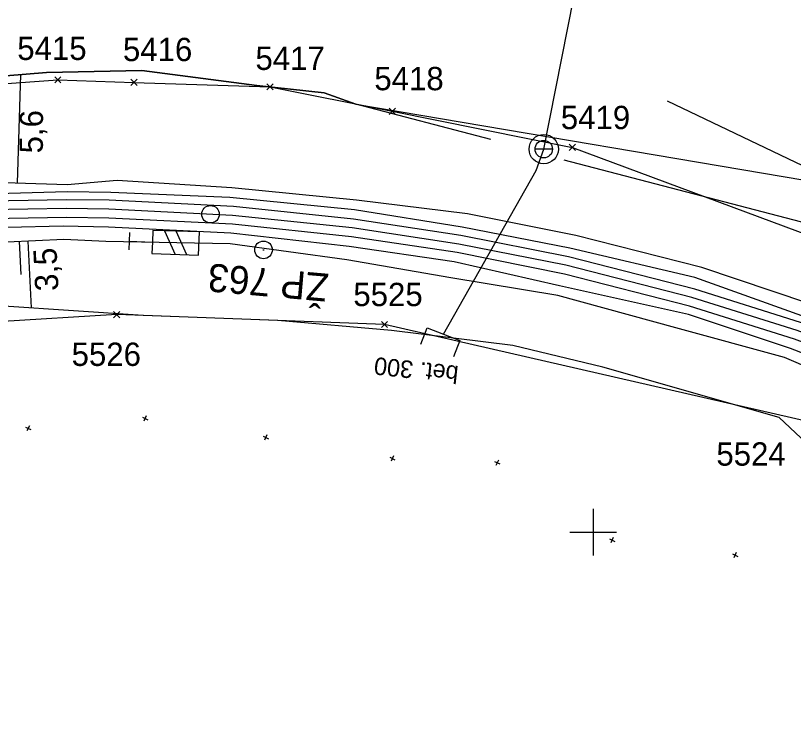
# Model space of a CAD drawing. Extents: x -805011 to -803920, y -1150790 to -1150234.
# Drawn here: x -804349.5 to -804282.8, y -1150516 to -1150455.7 of the extents above; entities that cross this region are included whole.
import ezdxf

# ---------------------------------------------------------------- set-up
doc = ezdxf.new("R2010")
doc.units = 0
for name, color, linetype in [('0381KM032-037P - Vrstva 1', 7, 'Continuous'), ('0381KM032-037P - Vrstva 17', 7, 'Continuous'), ('0381KM032-037P - Vrstva 19', 7, 'Continuous'), ('0381KM032-037P - Vrstva 4', 7, 'Continuous'), ('0381KM032-037P - Vrstva 41', 7, 'Continuous'), ('0381KM032-037P - Vrstva 43', 7, 'Continuous'), ('0381KM032-037P - Vrstva 48', 7, 'Continuous'), ('0381KM032-037P - Vrstva 49', 7, 'Continuous'), ('0381KM032-037P - Vrstva 51', 7, 'Continuous'), ('0381KM032-037P - Vrstva 7', 7, 'Continuous'), ('krizky_1000 - Vrstva 1', 7, 'Continuous'), ('szdc - hran DP', 7, 'Continuous'), ('szdc - szdc_cislo', 7, 'Continuous'), ('szdc - szdc_krizek', 7, 'Continuous'), ('vyt_sit - stávající', 7, 'Continuous')]:
    doc.layers.add(name, color=color, linetype=linetype)

msp = doc.modelspace()

# ---------------------------------------------------------------- linework, layer by layer
at = {"layer": '0381KM032-037P - Vrstva 1'}
for points in [[(-804345.19, -1150472.22), (-804355.1, -1150472.39), (-804364.37, -1150472.93), (-804373.68, -1150473.77), (-804382.25, -1150474.73), (-804390.38, -1150475.71), (-804394.38, -1150476.22)], [(-804222.979, -1150515.095), (-804226.42, -1150512.48), (-804234.26, -1150506.83), (-804242.54, -1150501.49), (-804250.96, -1150496.61), (-804260.8, -1150491.55), (-804271.59, -1150486.76), (-804282.48, -1150482.69), (-804291.53, -1150479.85), (-804302.34, -1150477.08), (-804311.51, -1150475.27), (-804320.67, -1150473.88), (-804330.92, -1150472.81), (-804341.55, -1150472.27), (-804345.19, -1150472.22)]]:
    msp.add_lwpolyline(points, dxfattribs=at)
at = {"layer": '0381KM032-037P - Vrstva 17'}
msp.add_line((-804323.06, -1150462.29), (-804328.85, -1150461.67), dxfattribs=at)
for points in [[(-804328.85, -1150461.67), (-804338.71, -1150460.38), (-804346.87, -1150460.56), (-804368.54, -1150462.33)], [(-804308.78, -1150466.29), (-804320.34, -1150463.27), (-804323.06, -1150462.29)], [(-804223.8, -1150504.14), (-804238.39, -1150493.96), (-804260.56, -1150483.05), (-804280.24, -1150473.89), (-804302.47, -1150468.07)]]:
    msp.add_lwpolyline(points, dxfattribs=at)
at = {"layer": '0381KM032-037P - Vrstva 19'}
msp.add_line((-804304.23, -1150467.13), (-804292.588, -1150408.116), dxfattribs=at)
msp.add_lwpolyline([(-804312.83, -1150483), (-804304.87, -1150468.97), (-804304.23, -1150467.13)], dxfattribs=at)
at = {"layer": '0381KM032-037P - Vrstva 4'}
for points in [[(-804225.7, -1150511.47), (-804233.93, -1150505.38), (-804241.84, -1150500.35), (-804251.18, -1150495.03), (-804260.27, -1150490.25), (-804271.39, -1150485.02), (-804282.1, -1150481.42), (-804291.28, -1150478.15), (-804302, -1150475.62), (-804311.22, -1150473.82), (-804320.47, -1150472.35), (-804331.17, -1150471.28), (-804341.36, -1150470.84), (-804345.11, -1150470.79), (-804355.15, -1150471.09), (-804364.49, -1150471.64), (-804373.72, -1150472.46), (-804382.56, -1150473.46), (-804390.64, -1150474.3), (-804394.58, -1150474.82), (-804430.68, -1150479.4), (-804471.16, -1150484.87), (-804515.79, -1150490.21)], [(-804222.47, -1150514.31), (-804225.93, -1150511.88), (-804233.81, -1150506.22), (-804242.12, -1150500.85), (-804250.57, -1150495.96), (-804260.44, -1150490.89), (-804271.28, -1150486.07), (-804282.21, -1150481.99), (-804291.28, -1150479.14), (-804302.11, -1150476.36), (-804311.33, -1150474.54), (-804320.55, -1150473.14), (-804330.83, -1150472.06), (-804341.5, -1150471.52), (-804345.16, -1150471.47), (-804355.1, -1150471.64), (-804364.39, -1150472.17), (-804373.73, -1150473.02), (-804382.33, -1150473.97), (-804390.45, -1150474.97), (-804394.45, -1150475.48), (-804430.79, -1150480.07), (-804470.48, -1150485.06), (-804515.61, -1150490.8)], [(-804223.37, -1150515.97), (-804226.85, -1150513.1), (-804234.67, -1150507.48), (-804242.93, -1150502.16), (-804251.31, -1150497.29), (-804261.13, -1150492.25), (-804271.85, -1150487.49), (-804282.71, -1150483.42), (-804291.73, -1150480.59), (-804302.46, -1150477.85), (-804311.66, -1150476.01), (-804320.71, -1150474.65), (-804330.94, -1150473.58), (-804341.55, -1150473.05), (-804345.16, -1150472.99), (-804355.02, -1150473.16), (-804364.28, -1150473.69), (-804373.57, -1150474.51), (-804382.12, -1150475.46), (-804390.26, -1150476.46), (-804394.25, -1150476.96), (-804430.61, -1150481.56), (-804470.33, -1150486.56), (-804515.43, -1150492.3)], [(-804235.83, -1150507.71), (-804243.11, -1150502.63), (-804252.43, -1150497.68), (-804261.4, -1150493.06), (-804272.11, -1150488.47), (-804283.06, -1150484.22), (-804291.82, -1150481.32), (-804302.89, -1150478.85), (-804311.92, -1150476.81), (-804320.92, -1150475.47), (-804331.06, -1150474.34), (-804341.56, -1150473.81), (-804345.45, -1150473.75), (-804355.04, -1150473.96), (-804364.32, -1150474.45), (-804373.64, -1150475.34), (-804382.1, -1150476.35), (-804390.24, -1150477.29), (-804394.24, -1150477.85), (-804430.45, -1150482.3), (-804470.19, -1150487.36), (-804515.37, -1150493.06)]]:
    msp.add_lwpolyline(points, dxfattribs=at)
at = {"layer": '0381KM032-037P - Vrstva 41'}
msp.add_line((-804303.48, -1150467.13), (-804304.98, -1150467.13), dxfattribs=at)
for radius in [1.259, 0.75]:
    msp.add_circle((-804304.23, -1150467.13), radius, dxfattribs=at)
at = {"layer": '0381KM032-037P - Vrstva 43'}
msp.add_lwpolyline([(-804314.771, -1150483.856), (-804314.229, -1150482.458), (-804311.431, -1150483.542), (-804311.974, -1150484.941)], dxfattribs=at)
at = {"layer": '0381KM032-037P - Vrstva 48'}
for p, q in [((-804349.36, -1150470.06), (-804349.076, -1150460.74)), ((-804348.485, -1150475.019), (-804348.208, -1150480.751)), ((-804349.234, -1150475.055), (-804349.098, -1150477.877))]:
    msp.add_line(p, q, dxfattribs=at)
at = {"layer": '0381KM032-037P - Vrstva 49'}
for p, q in [((-804338.656, -1150490.132), (-804338.204, -1150490.348)), ((-804338.322, -1150490.014), (-804338.538, -1150490.466)), ((-804348.686, -1150490.972), (-804348.234, -1150491.188)), ((-804348.352, -1150490.854), (-804348.568, -1150491.306)), ((-804327.972, -1150491.644), (-804328.188, -1150492.096)), ((-804328.306, -1150491.762), (-804327.854, -1150491.978)), ((-804317.446, -1150493.562), (-804316.994, -1150493.778)), ((-804317.112, -1150493.444), (-804317.328, -1150493.896)), ((-804308.456, -1150493.922), (-804308.004, -1150494.138)), ((-804308.122, -1150493.804), (-804308.338, -1150494.256)), ((-804298.596, -1150500.572), (-804298.144, -1150500.788)), ((-804298.262, -1150500.454), (-804298.478, -1150500.906)), ((-804288.046, -1150501.852), (-804287.594, -1150502.068)), ((-804287.712, -1150501.734), (-804287.928, -1150502.186))]:
    msp.add_line(p, q, dxfattribs=at)
for points in [[(-804541.806, -1150485.209), (-804536.325, -1150485.985), (-804530.599, -1150485.024), (-804524.609, -1150484.281), (-804503.761, -1150480.939), (-804473.972, -1150476.004), (-804446.961, -1150472.017), (-804437.24, -1150471.077), (-804431.751, -1150470.099), (-804429.717, -1150469.727), (-804427.076, -1150469.249), (-804388.45, -1150464.13), (-804374.42, -1150462.03), (-804368.54, -1150462.33), (-804346.87, -1150460.56), (-804338.71, -1150460.38), (-804328.85, -1150461.67), (-804323.06, -1150462.29), (-804320.34, -1150463.27)], [(-804328.85, -1150461.67), (-804323.06, -1150462.29), (-804320.34, -1150463.27)], [(-804320.34, -1150463.27), (-804278.12, -1150470.41)], [(-804221.1, -1150510.47), (-804225.19, -1150510.8), (-804233.52, -1150504.69), (-804241.09, -1150499.46), (-804250.66, -1150494.51), (-804260.04, -1150488.87), (-804271.07, -1150483.89), (-804281.58, -1150480.34), (-804290.68, -1150477.29), (-804301.47, -1150474.53), (-804310.76, -1150472.67), (-804320.3, -1150471.51), (-804330.99, -1150470.46), (-804340.83, -1150469.83), (-804345.1, -1150470.19), (-804354.95, -1150469.89)], [(-804226.97, -1150514.32), (-804233.94, -1150510.78), (-804236.52, -1150508.57), (-804243.93, -1150503.82), (-804252.72, -1150498.82), (-804262.25, -1150494.6), (-804273.33, -1150489.4), (-804283.59, -1150485.01), (-804292.89, -1150482.47), (-804303.02, -1150479.68), (-804312.2, -1150478.16), (-804321.12, -1150476.62), (-804331.14, -1150475.24), (-804341.8, -1150475.06), (-804345.41, -1150474.87), (-804355.14, -1150475.34), (-804364.22, -1150475.73), (-804373.58, -1150476.33), (-804382.14, -1150477.38), (-804390.01, -1150478.23), (-804394.36, -1150478.78), (-804430.35, -1150482.91), (-804470.16, -1150488.05), (-804515.21, -1150493.93)], [(-804276.15, -1150497.56), (-804284.03, -1150490.16), (-804299.15, -1150485.83), (-804306.89, -1150483.98), (-804317.28, -1150482.7), (-804327.05, -1150481.84), (-804338.6, -1150481.41), (-804350.55, -1150480.59), (-804360.54, -1150481.11), (-804374.96, -1150483.29), (-804385.39, -1150485.41), (-804391.71, -1150485.5), (-804430.73, -1150489.32), (-804470.3, -1150492.85), (-804514.17, -1150497.56)]]:
    msp.add_lwpolyline(points, dxfattribs=at)
at = {"layer": '0381KM032-037P - Vrstva 51'}
msp.add_lwpolyline([(-804222.47, -1150514.31), (-804222.23, -1150513.73), (-804221.1, -1150510.47), (-804220.62, -1150508.07), (-804220.01, -1150502.88), (-804222.18, -1150500.57), (-804227.38, -1150496.55), (-804235.69, -1150490.06), (-804246.55, -1150486.97), (-804255.48, -1150481.87), (-804266.7, -1150476.32), (-804278.12, -1150470.41), (-804293.62, -1150463)], dxfattribs=at)
at = {"layer": '0381KM032-037P - Vrstva 7'}
for p, q in [((-804339.775, -1150474.28), (-804339.825, -1150475.78)), ((-804336.768, -1150474.132), (-804335.836, -1150476.164)), ((-804334.837, -1150476.198), (-804335.769, -1150474.165))]:
    msp.add_line(p, q, dxfattribs=at)
msp.add_lwpolyline([(-804339.8, -1150475.03), (-804337.801, -1150475.097), (-804337.835, -1150476.097), (-804333.837, -1150476.232), (-804333.77, -1150474.233), (-804337.767, -1150474.098), (-804337.801, -1150475.097)], dxfattribs=at)
msp.add_circle((-804332.815, -1150472.714), 0.75, dxfattribs=at)
at = {"layer": 'krizky_1000 - Vrstva 1'}
for points in [[(-804300, -1150498), (-804300, -1150502)], [(-804302, -1150500), (-804298, -1150500)]]:
    msp.add_lwpolyline(points, dxfattribs=at)
at = {"layer": 'szdc - hran DP'}
for p, q in [((-804374.01, -1150463.14), (-804345.91, -1150461.18)), ((-804345.91, -1150461.18), (-804339.38, -1150461.4)), ((-804339.38, -1150461.4), (-804327.71, -1150461.78)), ((-804327.71, -1150461.78), (-804317.22, -1150463.88)), ((-804317.22, -1150463.88), (-804301.77, -1150466.98)), ((-804301.77, -1150466.98), (-804268.19, -1150479.5)), ((-804340.86, -1150481.33), (-804372.75, -1150483.24)), ((-804317.89, -1150482.17), (-804340.86, -1150481.33)), ((-804276.4, -1150491.69), (-804317.89, -1150482.17))]:
    msp.add_line(p, q, dxfattribs=at)
at = {"layer": 'szdc - szdc_krizek'}
for p, q in [((-804345.645, -1150461.445), (-804346.176, -1150460.915)), ((-804346.176, -1150461.445), (-804345.645, -1150460.915)), ((-804339.115, -1150461.665), (-804339.646, -1150461.135)), ((-804339.646, -1150461.665), (-804339.115, -1150461.135)), ((-804327.445, -1150462.045), (-804327.976, -1150461.515)), ((-804327.976, -1150462.045), (-804327.445, -1150461.515)), ((-804316.955, -1150464.145), (-804317.486, -1150463.615)), ((-804317.486, -1150464.145), (-804316.955, -1150463.615)), ((-804301.505, -1150467.245), (-804302.036, -1150466.715)), ((-804302.036, -1150467.245), (-804301.505, -1150466.715)), ((-804340.595, -1150481.595), (-804341.126, -1150481.065)), ((-804341.126, -1150481.595), (-804340.595, -1150481.065)), ((-804317.625, -1150482.435), (-804318.156, -1150481.905)), ((-804318.156, -1150482.435), (-804317.625, -1150481.905))]:
    msp.add_line(p, q, dxfattribs=at)
at = {"layer": 'vyt_sit - stávající'}
msp.add_line((-804328.316, -1150475.773), (-804328.216, -1150475.773), dxfattribs=at)
msp.add_circle((-804328.266, -1150475.773), 0.756, dxfattribs=at)

# ---------------------------------------------------------------- texts
at = {"layer": '0381KM032-037P - Vrstva 43'}
msp.add_text('bet. 300', height=1.5, rotation=173.80264, dxfattribs=at).set_placement((-804311.481, -1150485.744))
at = {"layer": '0381KM032-037P - Vrstva 48'}
for s, rotation, p in [('5,6', 89.66954, (-804347.198, -1150467.502)), ('3,5', 92.76548, (-804345.847, -1150479.262))]:
    msp.add_text(s, height=2, rotation=rotation, dxfattribs=at).set_placement(p)
at = {"layer": 'szdc - szdc_cislo'}
for s, p in [('5415', (-804349.392, -1150459.48)), ('5416', (-804340.327, -1150459.579)), ('5417', (-804328.961, -1150460.334)), ('5418', (-804318.762, -1150462.077)), ('5419', (-804302.767, -1150465.413)), ('5525', (-804320.564, -1150480.599)), ('5526', (-804344.731, -1150485.728)), ('5524', (-804289.422, -1150494.283))]:
    msp.add_text(s, height=2, dxfattribs=at).set_placement(p)
at = {"layer": 'vyt_sit - stávající'}
msp.add_text('ŽP 763', height=2.4, rotation=175, dxfattribs=at).set_placement((-804322.606, -1150477.832))

doc.saveas('drawing.dxf')
